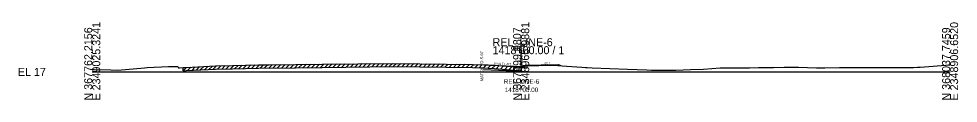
# Model space of a CAD drawing. Extents: x -26 to 403, y -10 to 6565.
# Drawn here: x -25.7 to 302.8, y 490.3 to 517.3 of the extents above; entities that cross this region are included whole.
import ezdxf

# ---------------------------------------------------------------- set-up
doc = ezdxf.new("R2010")
doc.units = 0
for name, color, linetype in [('RD_GPK_XS_Cell', 7, 'Continuous'), ('RD_XS_Base', 7, 'Continuous'), ('RD_XS_CurbBase', 7, 'Continuous'), ('RD_XS_CurbFront', 7, 'Continuous'), ('RD_XS_CurbTop', 7, 'Continuous'), ('RD_XS_EarthShd', 7, 'Continuous'), ('RD_XS_ExGround', 7, 'Continuous'), ('RD_XS_ExPaveRet', 7, 'Continuous'), ('RD_XS_MatchLine', 7, 'Continuous'), ('RD_XS_Pave', 7, 'Continuous'), ('RD_XS_SW', 7, 'Continuous'), ('RD_XS_SWbase', 7, 'Continuous'), ('RD_XS_TieSlope', 7, 'Continuous'), ('RD_XS_TX_Elev_EX', 7, 'Continuous'), ('RD_XS_TX_Elev_PR', 7, 'Continuous'), ('RD_XS_TX_MatchLine', 7, 'Continuous'), ('RD_XS_TX_Slope', 7, 'Continuous'), ('RD_XS_TX_Station', 7, 'Continuous'), ('RD_XS_TX_TOC', 7, 'Continuous')]:
    doc.layers.add(name, color=color, linetype=linetype)

msp = doc.modelspace()

# ---------------------------------------------------------------- linework, layer by layer
at = {"layer": 'RD_GPK_XS_Cell'}
for p, q in [((150, 500), (150, 509)), ((0, 500), (150, 500)), ((150, 500), (300, 500))]:
    msp.add_line(p, q, dxfattribs=at)
at = {"layer": 'RD_XS_Base'}
msp.add_line((136.85, 500.83), (150, 500.3), dxfattribs=at)
at = {"layer": 'RD_XS_CurbBase'}
for p, q in [((151.5, 501.33), (150, 501.41)), ((150, 500.3), (150, 501.41)), ((152, 501.33), (151.5, 501.33)), ((152, 502.33), (152, 501.33))]:
    msp.add_line(p, q, dxfattribs=at)
at = {"layer": 'RD_XS_CurbFront'}
msp.add_line((150, 501.41), (150, 501.91), dxfattribs=at)
at = {"layer": 'RD_XS_CurbTop'}
for p, q in [((150, 501.93), (150, 501.91)), ((150, 501.91), (151.42, 501.83)), ((151.42, 501.83), (151.5, 502.33)), ((151.5, 502.33), (152, 502.33))]:
    msp.add_line(p, q, dxfattribs=at)
at = {"layer": 'RD_XS_EarthShd'}
for p, q in [((152, 502.33), (157, 502.43)), ((162, 502.53), (163, 502.55))]:
    msp.add_line(p, q, dxfattribs=at)
at = {"layer": 'RD_XS_ExGround'}
msp.add_lwpolyline([(0, 500.94), (0.71, 500.82), (6.45, 500.69), (8.97, 500.63), (18.28, 501.47), (19.2, 501.56), (26.67, 501.85), (29.38, 501.95), (29.94, 501.95), (30.12, 501.45), (30.55, 501.47), (31.79, 501.55), (32.88, 501.59), (43.09, 502.12), (49.01, 502.24), (58.16, 502.51), (59.48, 502.53), (61.86, 502.51), (80.36, 502.74), (105.4, 503), (132.94, 502.63), (138.48, 502.5), (140.57, 502.32), (149.14, 501.7), (150.1, 501.65), (150.64, 501.62), (150.8, 502.12), (151.3, 502.12), (152.85, 502.2), (156.21, 502.25), (158.92, 502.31), (161.19, 502.38), (165.96, 502.04), (171.23, 501.63), (172.47, 501.51), (173.08, 501.5), (174.79, 501.47), (187.2, 501.02), (193.93, 500.76), (195.59, 500.62), (202.43, 500.57), (203.27, 500.63), (204.03, 500.65), (209.17, 500.84), (213.77, 501), (219.62, 501.46), (223.11, 501.46), (225.16, 501.43), (229.88, 501.4), (233.04, 501.55), (235.29, 501.55), (238.24, 501.51), (241.96, 501.64), (247.04, 501.65), (253.31, 501.48), (256.16, 501.47), (261.35, 501.53), (264.2, 501.52), (273.47, 501.5), (274.1, 501.5), (274.72, 501.51), (277.94, 501.53), (287.19, 501.6), (288.59, 501.7), (289.56, 501.72), (300, 502.43)], dxfattribs=at)
at = {"layer": 'RD_XS_ExPaveRet'}
for p, q in [((73.79, 501.52), (74.95, 502.67)), ((75.29, 501.53), (76.45, 502.69)), ((76.79, 501.55), (77.95, 502.71)), ((78.29, 501.57), (79.45, 502.73)), ((79.79, 501.59), (80.95, 502.74)), ((81.29, 501.6), (82.45, 502.76)), ((82.79, 501.62), (83.95, 502.78)), ((84.29, 501.64), (85.45, 502.79)), ((85.79, 501.65), (86.95, 502.81)), ((87.29, 501.67), (88.45, 502.82)), ((88.79, 501.68), (89.95, 502.84)), ((90.29, 501.7), (91.45, 502.85)), ((91.79, 501.71), (92.95, 502.87)), ((93.29, 501.73), (94.45, 502.89)), ((94.79, 501.75), (95.95, 502.9)), ((96.29, 501.76), (97.45, 502.92)), ((97.79, 501.78), (98.95, 502.93)), ((99.29, 501.79), (100.45, 502.95)), ((100.79, 501.81), (101.95, 502.96)), ((102.29, 501.82), (103.45, 502.98)), ((103.79, 501.84), (104.95, 502.99)), ((105.29, 501.86), (106.42, 502.99)), ((106.79, 501.84), (107.92, 502.97)), ((108.29, 501.82), (109.42, 502.95)), ((109.79, 501.8), (110.92, 502.93)), ((111.29, 501.78), (112.42, 502.91)), ((112.79, 501.76), (113.92, 502.89)), ((114.29, 501.74), (115.42, 502.87)), ((115.79, 501.72), (116.92, 502.85)), ((117.29, 501.7), (118.42, 502.82)), ((118.79, 501.68), (119.92, 502.8)), ((120.29, 501.66), (121.42, 502.78)), ((121.79, 501.64), (122.92, 502.76)), ((123.29, 501.62), (124.42, 502.74)), ((124.79, 501.6), (125.92, 502.72)), ((126.29, 501.58), (127.42, 502.7)), ((127.79, 501.56), (128.92, 502.68)), ((129.29, 501.54), (130.42, 502.66)), ((31.79, 500.4), (32.99, 501.6)), ((31.79, 500.4), (31.79, 501.55)), ((31.79, 500.4), (32.88, 500.45)), ((32.88, 500.45), (43.09, 500.97)), ((33.29, 500.47), (34.5, 501.67)), ((34.79, 500.55), (36, 501.75)), ((36.29, 500.62), (37.5, 501.83)), ((37.79, 500.7), (39, 501.91)), ((39.29, 500.78), (40.5, 501.98)), ((40.79, 500.86), (42, 502.06)), ((42.29, 500.93), (43.49, 502.13)), ((43.09, 500.97), (49.01, 501.1)), ((43.79, 500.99), (44.96, 502.16)), ((45.29, 501.02), (46.46, 502.19)), ((46.79, 501.05), (47.96, 502.22)), ((48.29, 501.08), (49.46, 502.26)), ((49.01, 501.1), (58.16, 501.37)), ((49.79, 501.12), (50.97, 502.3)), ((51.29, 501.17), (52.47, 502.34)), ((52.79, 501.21), (53.97, 502.39)), ((54.29, 501.25), (55.47, 502.43)), ((55.79, 501.3), (56.97, 502.48)), ((57.29, 501.34), (58.47, 502.52)), ((58.16, 501.37), (59.48, 501.39)), ((58.79, 501.38), (59.94, 502.53)), ((59.48, 501.39), (61.86, 501.37)), ((60.29, 501.38), (61.43, 502.52)), ((61.79, 501.37), (62.95, 502.53)), ((61.86, 501.37), (80.36, 501.59)), ((63.29, 501.39), (64.45, 502.55)), ((64.79, 501.41), (65.95, 502.56)), ((66.29, 501.42), (67.45, 502.58)), ((67.79, 501.44), (68.95, 502.6)), ((69.29, 501.46), (70.45, 502.62)), ((70.79, 501.48), (71.95, 502.64)), ((72.29, 501.5), (73.45, 502.65)), ((80.36, 501.59), (105.4, 501.86)), ((105.4, 501.86), (132.94, 501.49)), ((130.79, 501.52), (131.92, 502.64)), ((132.29, 501.5), (133.42, 502.62)), ((132.94, 501.49), (138.48, 501.35)), ((133.79, 501.47), (134.91, 502.58)), ((135.29, 501.43), (136.41, 502.55)), ((136.79, 501.39), (137.91, 502.51)), ((138.29, 501.36), (139.36, 502.42)), ((138.48, 501.35), (140.57, 501.17)), ((139.79, 501.24), (140.85, 502.3)), ((140.57, 501.17), (149.14, 500.55)), ((141.29, 501.12), (142.36, 502.19)), ((142.79, 501.01), (143.86, 502.08)), ((144.29, 500.9), (145.36, 501.97)), ((145.79, 500.8), (146.86, 501.86)), ((147.29, 500.69), (148.36, 501.75)), ((149.14, 501.7), (149.14, 500.55))]:
    msp.add_line(p, q, dxfattribs=at)
at = {"layer": 'RD_XS_MatchLine'}
msp.add_line((136.92, 502.47), (136.92, 502.53), dxfattribs=at)
at = {"layer": 'RD_XS_Pave'}
msp.add_line((136.92, 502.47), (150, 501.93), dxfattribs=at)
at = {"layer": 'RD_XS_SW'}
msp.add_line((157, 502.43), (162, 502.53), dxfattribs=at)
at = {"layer": 'RD_XS_SWbase'}
for p, q in [((157, 502.1), (157, 502.43)), ((162, 502.2), (157, 502.1)), ((162, 502.53), (162, 502.2))]:
    msp.add_line(p, q, dxfattribs=at)
at = {"layer": 'RD_XS_TieSlope'}
msp.add_line((163, 502.55), (163.7, 502.2), dxfattribs=at)

# ---------------------------------------------------------------- texts
at = {"layer": 'RD_GPK_XS_Cell'}
for s, p in [('E 2349025.3241', (2.8, 490)), ('E 2348965.9881', (152.8, 490)), ('E 2348906.6520', (302.8, 490)), ('N 367762.2156', (0, 490)), ('N 367899.9807', (150, 490)), ('N 368037.7459', (300, 490))]:
    msp.add_text(s, height=2.8, rotation=90, dxfattribs=at).set_placement(p)
for s, p in [('REL_LINE-6', (140, 509)), ('1418+00.00 / 1', (140, 506.2)), ('EL 17', (-26, 498.6))]:
    msp.add_text(s, height=2.8, dxfattribs=at).set_placement(p)
at = {"layer": 'RD_XS_TX_Elev_EX'}
msp.add_text('18.65', height=1, rotation=90, dxfattribs=at).set_placement((150.5, 501.65))
at = {"layer": 'RD_XS_TX_Elev_PR'}
msp.add_text(' 18.93', height=1.2, rotation=90, dxfattribs=at).set_placement((151.2, 505.38))
at = {"layer": 'RD_XS_TX_MatchLine'}
msp.add_text('MATCH TO S-97', height=1, rotation=90, dxfattribs=at).set_placement((136.71, 496.76))
at = {"layer": 'RD_XS_TX_Slope'}
for s, rotation, p in [('0.041 FT./FT.', 357.6676, (140.44, 502.57)), ('50:1', 1.1458, (158.21, 502.69))]:
    msp.add_text(s, height=0.75, rotation=rotation, dxfattribs=at).set_placement(p)
at = {"layer": 'RD_XS_TX_Station'}
for s, p in [('REL_LINE-6', (143.92, 495.83)), ('1418+00.00', (144.23, 492.93))]:
    msp.add_text(s, height=1.6, dxfattribs=at).set_placement(p)
at = {"layer": 'RD_XS_TX_TOC'}
msp.add_text('TOCRT', height=0.05, dxfattribs=at).set_placement((151.22, 502.28))

doc.saveas('drawing.dxf')
